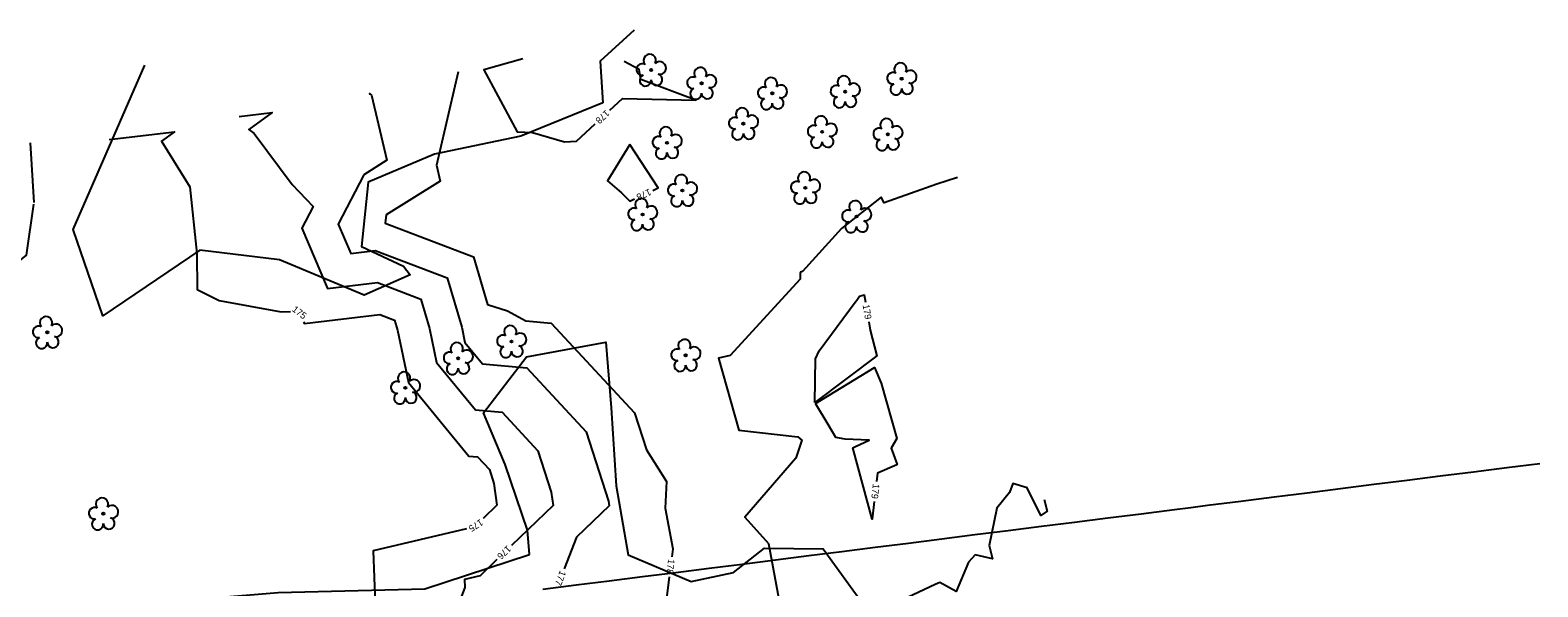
# Model space of a CAD drawing. Extents: x 2086416 to 2115205, y 575507 to 632762.
# Drawn here: x 2112506.7 to 2112956.5, y 581854.9 to 582021 of the extents above; entities that cross this region are included whole.
import ezdxf

# ---------------------------------------------------------------- set-up
doc = ezdxf.new("R2010")
doc.units = 0
for name, color, linetype in [('DTM Contours Major', 7, 'Continuous'), ('DTM Contours Major Text', 7, 'Continuous'), ('DTM Contours Minor', 7, 'Continuous'), ('DTM Contours Minor Text', 7, 'Continuous'), ('Exist Hydro Stream or Body of Water', 7, 'Continuous'), ('Exist Hydrographic FEMA Cross Section', 7, 'Continuous'), ('Exist Vegetation Tree CELL', 7, 'Continuous'), ('Exist Vegetation Woods Line', 7, 'Continuous')]:
    doc.layers.add(name, color=color, linetype=linetype)

# ---------------------------------------------------------------- blocks, each defined once
blk = doc.blocks.new('EXIST VEGETATION TREE')
at = {"layer": 'Exist Vegetation Tree CELL'}
blk.add_line((0, 0), (0, 0), dxfattribs=at)
blk.add_circle((0, 0), 0.00652, dxfattribs=at)
for centre, radius, start, end in [((-0.0077, 0.0575), 0.0371, 330.16508, 219.71335), ((-0.0521, 0.0031), 0.0345, 62.66361, 279.3457), ((0.051, 0.0118), 0.038, 257.1011, 134.19993), ((-0.0341, -0.0624), 0.0338, 111.56708, 6.23104), ((0.0335, -0.058), 0.034, 181.28216, 74.55999)]:
    blk.add_arc(centre, radius, start, end, dxfattribs=at)

msp = doc.modelspace()

# ---------------------------------------------------------------- linework, layer by layer
at = {"layer": 'DTM Contours Major'}
for points in [[(2112530.33, 581988.32), (2112549.79, 581990.63), (2112545.96, 581987.84), (2112554.39, 581974.22), (2112556.43, 581954.31), (2112556.54, 581943.61), (2112563.16, 581940.32), (2112581.6, 581936.89), (2112584.37, 581937.01)], [(2112588.3, 581933.96), (2112588.54, 581933.4), (2112611.09, 581936.12), (2112615.45, 581934.46), (2112616.32, 581931.49), (2112619.57, 581915.83), (2112637.59, 581893.89), (2112640.23, 581893.66), (2112643.78, 581889.84), (2112645.11, 581885.71), (2112646, 581879.24), (2112641.84, 581875.22)], [(2112809.21, 581880.92), (2112810.15, 581877.4), (2112808.25, 581876.11), (2112804.19, 581884.42), (2112799.94, 581885.7), (2112798.96, 581883.05), (2112795.09, 581878.3), (2112792.8, 581867.19), (2112793.8, 581863.22), (2112788.72, 581864.42), (2112786.67, 581862.19), (2112783.05, 581853.47), (2112778.14, 581856.17), (2112776.69, 581855.59), (2112770.17, 581852.49), (2112764.94, 581849.97), (2112763.7, 581843.17), (2112762.85, 581841.49), (2112758.53, 581840.84), (2112753.83, 581839.3)], [(2112636.91, 581872.16), (2112609.11, 581865.6), (2112609.65, 581849.73), (2112605.74, 581839.73), (2112603.91, 581826.98), (2112600.43, 581825.74), (2112595.52, 581824.65), (2112581.05, 581823.24), (2112575.88, 581822.78), (2112572.42, 581822.47)]]:
    msp.add_lwpolyline(points, dxfattribs=at)
at = {"layer": 'DTM Contours Minor'}
for points in [[(2112634.45, 582008.48), (2112627.92, 581980.65), (2112629.04, 581975.94), (2112612.99, 581965.84), (2112612.66, 581963.36), (2112639.04, 581953.3), (2112643.19, 581939.14), (2112649.11, 581937.25), (2112654.63, 581934.18), (2112662.19, 581933.53), (2112687.01, 581906.75), (2112690.57, 581895.74), (2112696.57, 581886.25), (2112696.17, 581878.3), (2112698.48, 581866.21), (2112698.18, 581863.81)], [(2112653.7, 582012.41), (2112642.08, 582009.12), (2112652.06, 581990.6), (2112656.59, 581990.41), (2112666.11, 581987.66), (2112669.76, 581987.86), (2112675.29, 581992.98)], [(2112679.7, 581997.06), (2112683.5, 582000.58), (2112705.37, 582000.1), (2112688.91, 582006.27), (2112688.46, 582009.25), (2112683.91, 582011.56)], [(2112607.92, 582002.07), (2112608.11, 582002.1), (2112607.98, 582002), (2112608.07, 582001.93), (2112608.55, 582001.6), (2112613.18, 581982.13), (2112606.28, 581977.79), (2112598.66, 581963.08), (2112602.41, 581954.36), (2112609.63, 581955.23), (2112631.18, 581947.02), (2112635.49, 581932.32), (2112636.43, 581927.76), (2112641.68, 581921.37), (2112654.87, 581920.24), (2112672.6, 581901.11), (2112679.28, 581880.46), (2112679.47, 581879.08), (2112669.7, 581869.66), (2112666.03, 581860.19)], [(2112569.13, 581995.2), (2112578.95, 581996.36), (2112571.97, 581991.28), (2112573.56, 581990.15), (2112584.87, 581974.86), (2112591.12, 581968.36), (2112587.74, 581961.85), (2112595.48, 581943.88), (2112610.36, 581945.68), (2112623.31, 581940.74), (2112625.9, 581931.9), (2112628, 581921.8), (2112639.64, 581907.63), (2112647.55, 581906.95), (2112658.19, 581895.47), (2112662.19, 581883.08), (2112662.73, 581879.16), (2112650.29, 581867.15)], [(2112685.61, 581986.83), (2112679.02, 581975.97), (2112683.15, 581972.38), (2112685.61, 581969.9), (2112687.08, 581970.59)], [(2112692.52, 581973.13), (2112694.14, 581973.88), (2112685.61, 581986.83)], [(2112783.36, 581977.02), (2112777.19, 581974.97), (2112761.48, 581969.46), (2112760.6, 581971.11), (2112748.83, 581961.81), (2112737.15, 581948.97), (2112737.17, 581948.9), (2112736.59, 581948.77), (2112736.48, 581948.58), (2112736.45, 581946.62), (2112715.55, 581923.9), (2112712.14, 581923.08), (2112718.12, 581901.59), (2112735.77, 581899.6), (2112736.98, 581898.61), (2112735.12, 581893.24), (2112719.92, 581875.62), (2112727.03, 581867.76), (2112730.62, 581848.49), (2112730.03, 581845.59), (2112728.71, 581844.64)], [(2112740.87, 581909.91), (2112741.04, 581922.86), (2112742.15, 581925.25), (2112752.84, 581939.75), (2112753.33, 581940.44), (2112754.21, 581941.58), (2112755.57, 581941.96), (2112755.94, 581939.82)], [(2112756.96, 581933.91), (2112757.38, 581931.47), (2112759.31, 581923.8), (2112740.87, 581909.91)], [(2112741.03, 581909.53), (2112758.65, 581920.34), (2112760.58, 581915.64), (2112765.28, 581899.13), (2112763.57, 581896.22), (2112765.38, 581891.36), (2112765.35, 581891.28), (2112759.53, 581888.79), (2112759.25, 581886.28)], [(2112758.57, 581880.32), (2112757.97, 581875.07), (2112752.2, 581896.38), (2112753, 581896.77), (2112757.02, 581898.67), (2112749.9, 581898.97), (2112747.13, 581899.46), (2112744.8, 581903.27), (2112741.03, 581909.53)], [(2112645.97, 581862.98), (2112640.96, 581858.15), (2112636.36, 581857.07), (2112636.44, 581854.64), (2112629.82, 581837.7), (2112626.77, 581831.69), (2112626.76, 581830.54), (2112626.08, 581830.21), (2112625.08, 581829.94), (2112613.9, 581825.94), (2112596.28, 581822.03), (2112595.89, 581821.94), (2112595.73, 581821.92), (2112595.14, 581821.86), (2112576.22, 581820.18), (2112561.06, 581818.84), (2112546.35, 581817.4), (2112536.87, 581816.69), (2112528.13, 581815.99), (2112511.43, 581814.74), (2112498.22, 581813.69), (2112487.5, 581812.49), (2112476.22, 581810.87), (2112468.78, 581810.01)], [(2112697.42, 581857.86), (2112695.28, 581840.91), (2112692.79, 581837.25), (2112690.56, 581835.55), (2112688.56, 581835.37), (2112677.37, 581832.83), (2112675.87, 581832.17), (2112672.05, 581831.94), (2112651.52, 581827.43), (2112646.49, 581826.71), (2112636.31, 581823.94), (2112625.7, 581822.28), (2112615.6, 581819.85), (2112596.09, 581816.86), (2112588.69, 581816.19), (2112577.09, 581814.47), (2112556.48, 581811.43), (2112547.27, 581811.07), (2112547.04, 581811.16), (2112539.5, 581810.54), (2112538.76, 581810.37), (2112520.89, 581808.45), (2112518.28, 581808.23), (2112517.45, 581808.07)]]:
    msp.add_lwpolyline(points, dxfattribs=at)
at = {"layer": 'Exist Hydro Stream or Body of Water'}
for points in [[(2112507.88, 581969.56), (2112506.82, 581987.31)], [(2112499.44, 581880.39), (2112494.24, 581935.71), (2112497.4, 581947.12), (2112505.67, 581953.82), (2112507.86, 581969.07)]]:
    msp.add_lwpolyline(points, dxfattribs=at)
at = {"layer": 'Exist Hydrographic FEMA Cross Section'}
msp.add_lwpolyline([(2112957.19, 581891.61), (2112947.27, 581890.36), (2112937.35, 581889.11), (2112927.44, 581887.86), (2112917.52, 581886.61), (2112907.6, 581885.35), (2112897.69, 581884.1), (2112887.77, 581882.85), (2112877.85, 581881.6), (2112867.94, 581880.35), (2112858.02, 581879.1), (2112853.06, 581878.47), (2112848.1, 581877.85), (2112838.18, 581876.59), (2112828.27, 581875.34), (2112818.35, 581874.09), (2112808.43, 581872.84), (2112798.52, 581871.59), (2112788.6, 581870.34), (2112778.68, 581869.08), (2112768.77, 581867.83), (2112758.85, 581866.58), (2112748.93, 581865.33), (2112739.02, 581864.08), (2112729.1, 581862.83), (2112719.18, 581861.57), (2112709.27, 581860.32), (2112699.35, 581859.07), (2112689.43, 581857.82), (2112679.52, 581856.57), (2112669.6, 581855.32), (2112659.68, 581854.07)], dxfattribs=at)
at = {"layer": 'Exist Vegetation Tree CELL'}
for p, q in [((2112691.99, 582009.07), (2112691.99, 582009.07)), ((2112707.05, 582005.1), (2112707.05, 582005.1)), ((2112766.77, 582006.45), (2112766.77, 582006.45)), ((2112728.14, 582002.08), (2112728.14, 582002.08)), ((2112749.88, 582002.61), (2112749.88, 582002.61)), ((2112719.53, 581993.06), (2112719.53, 581993.06)), ((2112743.04, 581990.61), (2112743.04, 581990.61)), ((2112696.75, 581987.34), (2112696.75, 581987.34)), ((2112762.6, 581989.85), (2112762.6, 581989.85)), ((2112701.33, 581973.1), (2112701.33, 581973.1)), ((2112738.03, 581973.92), (2112738.03, 581973.92)), ((2112689.45, 581965.97), (2112689.45, 581965.97)), ((2112753.29, 581965.35), (2112753.29, 581965.35)), ((2112702.3, 581923.94), (2112702.3, 581923.94))]:
    msp.add_line(p, q, dxfattribs=at)
for centre in [(2112691.99, 582009.07), (2112707.05, 582005.1), (2112766.77, 582006.45), (2112728.14, 582002.08), (2112749.88, 582002.61), (2112719.53, 581993.06), (2112743.04, 581990.61), (2112762.6, 581989.85), (2112696.75, 581987.34), (2112701.33, 581973.1), (2112738.03, 581973.92), (2112689.45, 581965.97), (2112753.29, 581965.35), (2112702.3, 581923.94)]:
    msp.add_circle(centre, 0.326, dxfattribs=at)
for centre, radius, start, end in [((2112691.6, 582011.94), 1.86, 330.1651, 219.7134), ((2112689.38, 582009.22), 1.73, 62.6636, 279.3457), ((2112694.54, 582009.66), 1.9, 257.1011, 134.1999), ((2112706.66, 582007.97), 1.86, 330.1651, 219.7134), ((2112764.17, 582006.61), 1.73, 62.6636, 279.3457), ((2112766.39, 582009.33), 1.86, 330.1651, 219.7134), ((2112769.32, 582007.04), 1.9, 257.1011, 134.1999), ((2112690.29, 582005.95), 1.69, 111.5671, 6.231), ((2112693.66, 582006.17), 1.7, 181.2822, 74.56), ((2112704.44, 582005.25), 1.73, 62.6636, 279.3457), ((2112708.72, 582002.2), 1.7, 181.2822, 74.56), ((2112709.6, 582005.69), 1.9, 257.1011, 134.1999), ((2112725.53, 582002.24), 1.73, 62.6636, 279.3457), ((2112727.75, 582004.96), 1.86, 330.1651, 219.7134), ((2112730.69, 582002.67), 1.9, 257.1011, 134.1999), ((2112747.27, 582002.76), 1.73, 62.6636, 279.3457), ((2112749.49, 582005.48), 1.86, 330.1651, 219.7134), ((2112752.43, 582003.2), 1.9, 257.1011, 134.1999), ((2112765.07, 582003.33), 1.69, 111.5671, 6.231), ((2112768.44, 582003.55), 1.7, 181.2822, 74.56), ((2112705.34, 582001.98), 1.69, 111.5671, 6.231), ((2112726.43, 581998.96), 1.69, 111.5671, 6.231), ((2112729.81, 581999.19), 1.7, 181.2822, 74.56), ((2112748.17, 581999.49), 1.69, 111.5671, 6.231), ((2112751.55, 581999.71), 1.7, 181.2822, 74.56), ((2112716.93, 581993.21), 1.73, 62.6636, 279.3457), ((2112719.15, 581995.93), 1.86, 330.1651, 219.7134), ((2112722.08, 581993.65), 1.9, 257.1011, 134.1999), ((2112742.65, 581993.48), 1.86, 330.1651, 219.7134), ((2112696.37, 581990.21), 1.86, 330.1651, 219.7134), ((2112717.83, 581989.94), 1.69, 111.5671, 6.231), ((2112721.21, 581990.16), 1.7, 181.2822, 74.56), ((2112740.43, 581990.76), 1.73, 62.6636, 279.3457), ((2112745.59, 581991.2), 1.9, 257.1011, 134.1999), ((2112760, 581990), 1.73, 62.6636, 279.3457), ((2112762.22, 581992.72), 1.86, 330.1651, 219.7134), ((2112765.15, 581990.44), 1.9, 257.1011, 134.1999), ((2112694.15, 581987.49), 1.73, 62.6636, 279.3457), ((2112695.05, 581984.22), 1.69, 111.5671, 6.231), ((2112698.42, 581984.44), 1.7, 181.2822, 74.56), ((2112699.3, 581987.92), 1.9, 257.1011, 134.1999), ((2112741.33, 581987.49), 1.69, 111.5671, 6.231), ((2112744.71, 581987.71), 1.7, 181.2822, 74.56), ((2112760.9, 581986.73), 1.69, 111.5671, 6.231), ((2112764.28, 581986.95), 1.7, 181.2822, 74.56), ((2112700.94, 581975.97), 1.86, 330.1651, 219.7134), ((2112737.64, 581976.8), 1.86, 330.1651, 219.7134), ((2112698.72, 581973.25), 1.73, 62.6636, 279.3457), ((2112703.88, 581973.69), 1.9, 257.1011, 134.1999), ((2112735.42, 581974.08), 1.73, 62.6636, 279.3457), ((2112736.33, 581970.8), 1.69, 111.5671, 6.231), ((2112739.7, 581971.02), 1.7, 181.2822, 74.56), ((2112740.58, 581974.51), 1.9, 257.1011, 134.1999), ((2112686.84, 581966.13), 1.73, 62.6636, 279.3457), ((2112689.06, 581968.85), 1.86, 330.1651, 219.7134), ((2112691.99, 581966.56), 1.9, 257.1011, 134.1999), ((2112699.62, 581969.98), 1.69, 111.5671, 6.231), ((2112703, 581970.2), 1.7, 181.2822, 74.56), ((2112752.9, 581968.22), 1.86, 330.1651, 219.7134), ((2112755.84, 581965.94), 1.9, 257.1011, 134.1999), ((2112687.74, 581962.85), 1.69, 111.5671, 6.231), ((2112691.12, 581963.07), 1.7, 181.2822, 74.56), ((2112750.68, 581965.5), 1.73, 62.6636, 279.3457), ((2112751.58, 581962.23), 1.69, 111.5671, 6.231), ((2112754.96, 581962.45), 1.7, 181.2822, 74.56), ((2112701.92, 581926.82), 1.86, 330.1651, 219.7134), ((2112699.7, 581924.1), 1.73, 62.6636, 279.3457), ((2112703.97, 581921.04), 1.7, 181.2822, 74.56), ((2112704.85, 581924.53), 1.9, 257.1011, 134.1999), ((2112700.6, 581920.82), 1.69, 111.5671, 6.231)]:
    msp.add_arc(centre, radius, start, end, dxfattribs=at)
at = {"layer": 'Exist Vegetation Woods Line'}
for points in [[(2112686.98, 582020.95), (2112676.77, 582011.73), (2112677.57, 581999.24)], [(2112677.57, 581999.24), (2112653.14, 581989.31), (2112627.34, 581983.99), (2112607.58, 581975.6), (2112605.63, 581956.42), (2112618.13, 581950.51), (2112620.06, 581947.91), (2112606.43, 581941.86), (2112581.12, 581952.43), (2112557.4, 581955.36), (2112528.38, 581935.68), (2112519.58, 581961.49), (2112540.98, 582010.48)], [(2112655.73, 581864.5), (2112655.15, 581871.73), (2112648.45, 581891.34), (2112642, 581906.74), (2112654.8, 581923.48), (2112678.53, 581927.89), (2112680.12, 581908.28), (2112681.57, 581885.02), (2112685.12, 581864.41), (2112703.96, 581856.48), (2112716.53, 581859.17), (2112725.8, 581866.44), (2112743.31, 581866.23), (2112755.55, 581849.31)], [(2112455.71, 581861.8), (2112519.59, 581848.11), (2112580.68, 581853.15), (2112624.48, 581854.23), (2112655.73, 581864.5)]]:
    msp.add_lwpolyline(points, dxfattribs=at)

# ---------------------------------------------------------------- block references
at = {"layer": 'Exist Vegetation Tree CELL', "xscale": 50, "yscale": 50}
for p in [(2112511.85, 581930.78), (2112650.35, 581928.07), (2112634.41, 581923.03), (2112618.69, 581914.24), (2112528.56, 581876.67)]:
    msp.add_blockref('EXIST VEGETATION TREE', p, dxfattribs=at)

# ---------------------------------------------------------------- texts
at = {"layer": 'DTM Contours Major Text'}
for rotation, p in [(322.2519, (2112584.7, 581937.32)), (211.8619, (2112641.08, 581875.19))]:
    msp.add_text('175', height=2, rotation=rotation, dxfattribs=at).set_placement(p)
at = {"layer": 'DTM Contours Minor Text'}
for s, rotation, p in [('178', 222.7914, (2112678.48, 581997.3)), ('178', 204.9808, (2112691.44, 581973.73)), ('179', 279.7954, (2112755.07, 581938.94)), ('179', 263.5174, (2112758.17, 581885.67)), ('176', 223.9707, (2112649.07, 581867.37)), ('177', 248.7915, (2112664.84, 581859.88)), ('178', 262.8009, (2112697.09, 581863.22))]:
    msp.add_text(s, height=2, rotation=rotation, dxfattribs=at).set_placement(p)

doc.saveas('drawing.dxf')
